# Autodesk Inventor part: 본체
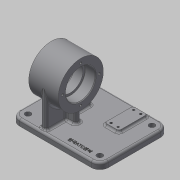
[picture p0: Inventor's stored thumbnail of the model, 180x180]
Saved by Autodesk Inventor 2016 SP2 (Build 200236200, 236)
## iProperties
Created: 2019-09
Part Number: 본체
Material: 알루미늄 6061
Document SubType Name: Modeling
Designer: mduedu
Density: 2.71 g/cm^3
Mass: 561.398 g
Surface Area: 499.749 cm^2
Volume: 207.158 cm^3
Appearance: 기본값
Author: mduedu
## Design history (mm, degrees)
sketch "스케치1"
  geometry: L1 (42, -62)-(-84, -62); L2 (-84, -62)-(-84, 36); L3 (-84, 36)-(42, 36); L4 (42, 36)-(42, -62); 1 further point
  constraints: 8 end point, 2 parallel, 1 horizontal, 1 perpendicular
  dimensions: "d0" = 36 distance from line of L3 point (0, 0); "d1" = 98 distance of L1.end L2.end; "d2" = 42 distance from line of L4 point (0, 0); "d3" = 126 distance of L2.end L3.end
extrude "돌출1" new body sketch "스케치1" distance "d4" = 9; taper "d5" = 0 deg
sketch "스케치2"
  geometry: L1 (0, -62)-(0, 36) reference; C1 r 32 at (59, 0); 1 further point
  constraints: 1 centre point, 1 horizontal alignment
  dimensions: "d6" = 64 diameter of C1; "d7" = 59 distance from line of L1 C1.centre
extrude "돌출2" join sketch "스케치2" stored distance "d8" = 42; taper "d9" = 0 deg
sketch "스케치3"
  geometry: L1 (-17, 4)-(17, 4); L2 (17, 4)-(17, -4); L3 (17, -4)-(-17, -4); L4 (-17, -4)-(-17, 4); L5 (-4, 32)-(4, 32); L6 (4, 32)-(4, -32); L7 (4, -32)-(-4, -32); L8 (-4, -32)-(-4, 32); 5 further points
  constraints: 16 end point, 4 midpoint, 4 parallel, 2 horizontal, 2 horizontal alignment, 2 perpendicular, 2 vertical alignment
  dimensions: "d10" = 8 distance of L5.start L5.end; "d12" = 8 distance of L1.end L2.end; "d13" = 34 distance of L2.end L3.end; "d14" = 64 distance of L5.end L6.end
extrude "돌출3" join sketch "스케치3" stored distance "d15" = 42; taper "d16" = 0 deg
sketch "스케치4"
  geometry: C1 r 32 at (0, 0) reference; C2 r 21 at (0, 0); 1 further point
  constraints: 1 centre point, 1 coincident
  dimensions: "d17" = 42 diameter of C2
extrude "돌출4" cut sketch "스케치4" distance "d18" = 15; taper "d19" = 0 deg
hole "구멍1" diameter "d22" = 36; stored, may be unused: countersink angle "d26" = 90 deg, drill point angle "d28" = 118 deg; dims "d20" = 10, "d21" = 10, "d23" = 6, "d24" = 4, "d25" = 2, "d27" = 8
fillet "모깎기1" dims "d29" = 0.3
chamfer "모따기1" distance "d30" = 1; stored, may be unused: second distance "d31" = 2, angle "d32" = 45 deg
sketch "스케치5" dims "d33" = 52
  geometry: C1 r 32 at (0, 0) reference; 3 further points
  constraints: 2 vertical alignment, 1 coincident, 2 other
hole "구멍2" sketch "스케치5" at (0, 26) diameter "d34" = 3.242; stored, may be unused: countersink angle "d38" = 90 deg, drill point angle "d40" = 118 deg; dims "d35" = 8, "d36" = 4, "d37" = 2, "d39" = 10
fillet "모깎기2" dims "d44" = 12
sketch "스케치6"
  geometry: L1 (-42, 50)-(-42, -24) reference; L2 (-30, -36)-(72, -36) reference; L3 (84, -24)-(84, 50) reference; L4 (72, 62)-(-30, 62) reference; L5 (17, 4)-(17, -4) reference; L6 (17, -4)-(4, -4) reference; L7 (4, -4)-(4, -32) reference; L8 (4, -32)-(-4, -32) reference; L9 (-4, -32)-(-4, -4) reference; L10 (-4, -4)-(-17, -4) reference; L11 (-17, -4)-(-17, 4) reference; L12 (-17, 4)-(-4, 4) reference; L13 (-4, 4)-(-4, 32) reference; L14 (-4, 32)-(4, 32) reference; L15 (4, 32)-(4, 4) reference; L16 (4, 4)-(17, 4) reference; A1 r 12 centre (-30, 50) between (-30, 62) and (-42, 50) reference; A2 r 12 centre (-30, -24) between (-42, -24) and (-30, -36) reference; A3 r 12 centre (72, -24) between (72, -36) and (84, -24) reference; A4 r 12 centre (72, 50) between (84, 50) and (72, 62) reference; 5 further points
  constraints: 4 coincident
hole "구멍3" sketch "스케치6" at (-30, 50), (72, 50), (72, -24), (-30, -24) diameter "d45" = 8; stored, may be unused: countersink angle "d49" = 90 deg, drill point angle "d51" = 118 deg; dims "d46" = 8, "d47" = 4, "d48" = 2, "d50" = 10
sketch "스케치7"
  geometry: L1 (38, 57)-(58, 57); L2 (58, 57)-(58, 17); L3 (58, 17)-(38, 17); L4 (38, 17)-(38, 57); L5 (72, 62)-(-30, 62) reference; 3 further points
  constraints: 8 end point, 2 midpoint, 2 parallel, 1 horizontal, 1 perpendicular
  dimensions: "d52" = 48 horizontal distance of point (48, 57) point (0, 0); "d53" = 20 distance of L1.start L1.end; "d54" = 40 distance of L1.end L2.end; "d55" = 25 distance from line of point (38, 37) L5
extrude "돌출5" join sketch "스케치7" distance "d56" = 3; taper "d57" = 0 deg
fillet "모깎기3" dims "d58" = 3
fillet "모깎기4" dims "d59" = 3
fillet "모깎기5" dims "d60" = 3
fillet "모깎기6" dims "d61" = 3
fillet "모깎기7" dims "d62" = 3
fillet "모깎기8" dims "d63" = 3
sketch "스케치8"
  geometry: L1 (72, 62)-(58.317, 62) reference; L2 (84, -24)-(84, 50) reference; C1 r 1.5 at (43, 53); C2 r 1.5 at (53, 21); 1 further point
  constraints: 2 centre point, 1 equal radius
  dimensions: "d64" = 3 diameter of C1; "d65" = 9 distance from line of C1.centre L1; "d66" = 32 vertical distance of C2.centre C1.centre; "d67" = 10 horizontal distance of C2.centre C1.centre; "d68" = 31 distance from line of L2 C2.centre
hole "구멍4" sketch "스케치8" at (43, 53), (53, 21) diameter "d69" = 3; stored, may be unused: countersink angle "d73" = 90 deg, drill point angle "d75" = 118 deg; dims "d70" = 8, "d71" = 4, "d72" = 2, "d74" = 6
sketch "스케치9"
  geometry: C1 r 1.5 at (43, 53) reference; C2 r 1.5 at (53, 21) reference; 3 further points
  constraints: 2 horizontal alignment, 2 vertical alignment
hole "구멍5" sketch "스케치9" at (53, 53), (43, 21) diameter "d76" = 3.242; stored, may be unused: countersink angle "d80" = 90 deg, drill point angle "d82" = 118 deg; dims "d77" = 6, "d78" = 4, "d79" = 2, "d81" = 8
sketch "스케치10"
  geometry: L1 (-30, -36)-(72, -36) reference; L2 (84, -24)-(84, 50) reference; 2 further points
  constraints: 1 other
  dimensions: "d83" = 10 distance from line of point (46, -26) L1; "d84" = 38 distance from line of point (46, -26) L2
feature "엠보싱1" sketch "스케치10" dims "d0" = 36, "d1" = 98, "d2" = 42, "d3" = 126, "d10" = 8, "d14" = 64, "d85" = 0.5, "d86" = 0
node "솔리드1"
mirror "대칭1"
pattern_circular "원형 패턴1" dims angle "d42" = 360 deg
mirror "대칭2"
node "투영된 루프1"
